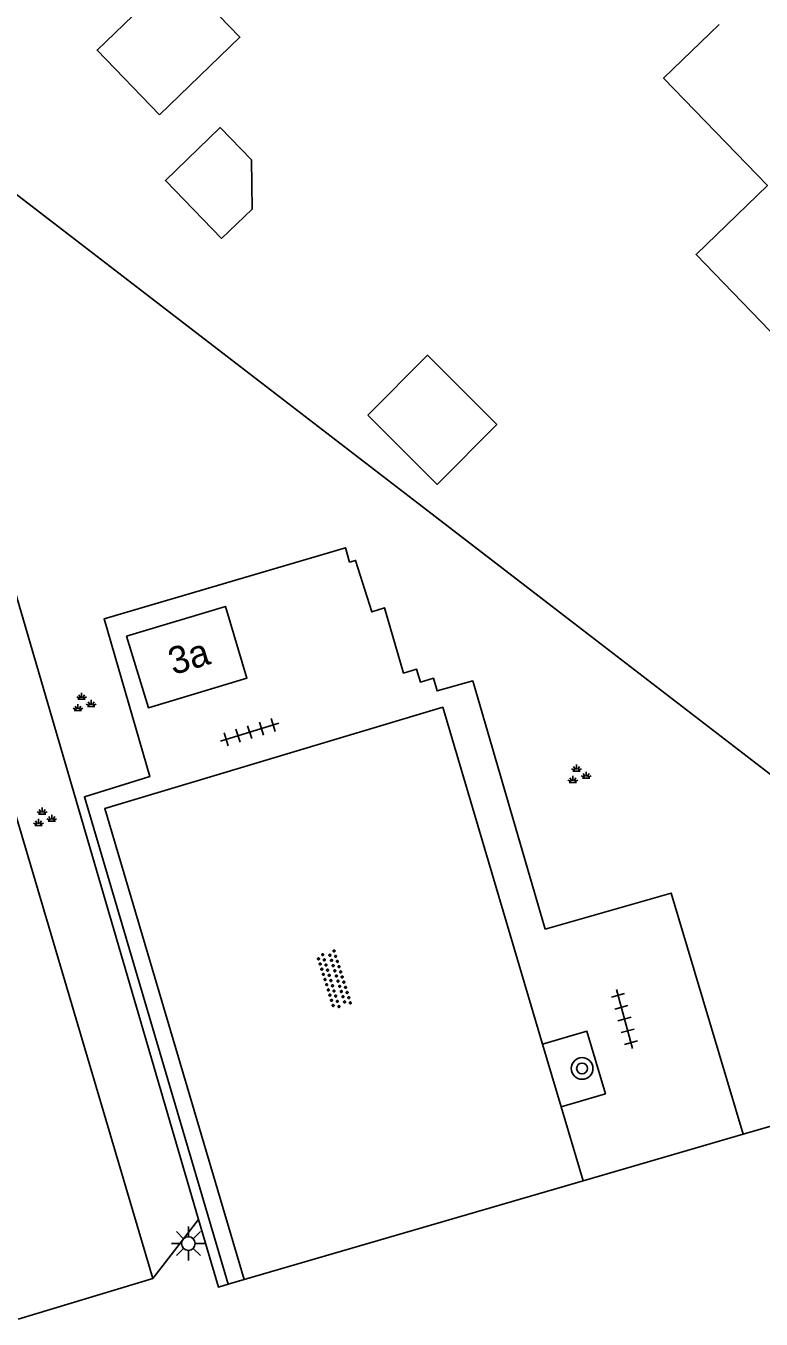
# Model space of a CAD drawing. Extents: x 137999 to 141000, y 397500 to 400501.
# Drawn here: x 138385.02 to 138412.07, y 399270.68 to 399318.29 of the extents above; entities that cross this region are included whole.
import ezdxf

# ---------------------------------------------------------------- set-up
doc = ezdxf.new("R2010")
doc.units = 0
for name, color, linetype in [('gg-afsc-hekwerk', 7, 'Continuous'), ('gg-anno-huisnummerreeks BGT', 7, 'Continuous'), ('gg-bbg-gedigitaliseerde bebouwing', 7, 'Continuous'), ('gg-bbg-gedigitaliseerde bijgebouw', 7, 'Continuous'), ('gg-bbg-hoofdgebouw', 7, 'Continuous'), ('gg-bbg-luifel en loopbrug', 7, 'Continuous'), ('gg-knt-bovenkant onderkant talud', 7, 'Continuous'), ('gg-knt-verharding', 7, 'Continuous'), ('gt-grn-groengrens', 7, 'Continuous'), ('gt-symb-boom', 7, 'Continuous'), ('gt-symb-groenvak', 7, 'Continuous'), ('gt-symb-lichtmast', 7, 'Continuous'), ('gt-symb-overige verharding', 7, 'Continuous'), ('gt-symb-tegel verharding', 7, 'Continuous')]:
    doc.layers.add(name, color=color, linetype=linetype)

# ---------------------------------------------------------------- blocks, each defined once
blk = doc.blocks.new('gt0-GRVAK')
at = {"layer": 'gt-symb-groenvak'}
for p, q in [((-0.11, 0.189), (-0.228, 0.24)), ((-0.182, 0.153), (0.088, 0.153)), ((-0.091, 0.211), (-0.156, 0.322)), ((-0.047, 0.214), (-0.047, 0.393)), ((-0.004, 0.211), (0.061, 0.322)), ((0.015, 0.189), (0.133, 0.24)), ((0.262, -0.052), (0.197, 0.059)), ((0.305, -0.049), (0.305, 0.13)), ((0.349, -0.052), (0.414, 0.059)), ((-0.245, -0.228), (-0.363, -0.177)), ((-0.318, -0.264), (-0.047, -0.264)), ((-0.226, -0.206), (-0.291, -0.095)), ((-0.183, -0.203), (-0.183, -0.024)), ((-0.139, -0.206), (-0.074, -0.095)), ((-0.12, -0.228), (-0.002, -0.177)), ((0.243, -0.074), (0.125, -0.023)), ((0.17, -0.11), (0.441, -0.11)), ((0.368, -0.074), (0.486, -0.023))]:
    blk.add_line(p, q, dxfattribs=at)
blk = doc.blocks.new('gt0-TEG1')
at = {"layer": 'gt-symb-tegel verharding'}
for p, q in [((-1.125, 0), (1.125, 0)), ((-0.9, -0.25), (-0.9, 0.25)), ((-0.45, -0.25), (-0.45, 0.25)), ((0, -0.25), (0, 0.25)), ((0.45, -0.25), (0.45, 0.25)), ((0.9, -0.25), (0.9, 0.25))]:
    blk.add_line(p, q, dxfattribs=at)
blk = doc.blocks.new('gt0-OVH')
at = {"layer": 'gt-symb-overige verharding'}
for points in [[(-0.972, 0.298), (-0.967, 0.308), (-0.965, 0.319), (-0.966, 0.33), (-0.971, 0.34), (-0.978, 0.348), (-0.988, 0.353), (-0.999, 0.355), (-1.01, 0.354), (-1.02, 0.349), (-1.028, 0.342), (-1.033, 0.332), (-1.035, 0.321), (-1.034, 0.31), (-1.029, 0.3), (-1.022, 0.292), (-1.012, 0.287), (-1.001, 0.285), (-0.99, 0.286), (-0.98, 0.291)], [(-0.872, 0.106), (-0.867, 0.116), (-0.865, 0.126), (-0.866, 0.137), (-0.871, 0.147), (-0.878, 0.156), (-0.888, 0.161), (-0.899, 0.163), (-0.91, 0.162), (-0.92, 0.157), (-0.928, 0.15), (-0.933, 0.14), (-0.935, 0.129), (-0.934, 0.118), (-0.929, 0.108), (-0.922, 0.1), (-0.912, 0.095), (-0.901, 0.092), (-0.89, 0.094), (-0.88, 0.098)], [(-0.772, 0.298), (-0.767, 0.308), (-0.765, 0.319), (-0.766, 0.33), (-0.771, 0.34), (-0.778, 0.348), (-0.788, 0.353), (-0.799, 0.355), (-0.81, 0.354), (-0.82, 0.349), (-0.828, 0.342), (-0.833, 0.332), (-0.835, 0.321), (-0.834, 0.31), (-0.829, 0.3), (-0.822, 0.292), (-0.812, 0.287), (-0.801, 0.285), (-0.79, 0.286), (-0.78, 0.291)], [(-0.672, 0.106), (-0.667, 0.116), (-0.665, 0.126), (-0.666, 0.137), (-0.671, 0.147), (-0.678, 0.156), (-0.688, 0.161), (-0.699, 0.163), (-0.71, 0.162), (-0.72, 0.157), (-0.728, 0.15), (-0.733, 0.14), (-0.735, 0.129), (-0.734, 0.118), (-0.729, 0.108), (-0.722, 0.1), (-0.712, 0.095), (-0.701, 0.092), (-0.69, 0.094), (-0.68, 0.098)], [(-0.572, 0.298), (-0.567, 0.308), (-0.565, 0.319), (-0.566, 0.33), (-0.571, 0.34), (-0.578, 0.348), (-0.588, 0.353), (-0.599, 0.355), (-0.61, 0.354), (-0.62, 0.349), (-0.628, 0.342), (-0.633, 0.332), (-0.635, 0.321), (-0.634, 0.31), (-0.629, 0.3), (-0.622, 0.292), (-0.612, 0.287), (-0.601, 0.285), (-0.59, 0.286), (-0.58, 0.291)], [(-0.472, 0.106), (-0.467, 0.116), (-0.465, 0.126), (-0.466, 0.137), (-0.471, 0.147), (-0.478, 0.156), (-0.488, 0.161), (-0.499, 0.163), (-0.51, 0.162), (-0.52, 0.157), (-0.528, 0.15), (-0.533, 0.14), (-0.535, 0.129), (-0.534, 0.118), (-0.529, 0.108), (-0.522, 0.1), (-0.512, 0.095), (-0.501, 0.092), (-0.49, 0.094), (-0.48, 0.098)], [(-0.372, 0.298), (-0.367, 0.308), (-0.365, 0.319), (-0.366, 0.33), (-0.371, 0.34), (-0.378, 0.348), (-0.388, 0.353), (-0.399, 0.355), (-0.41, 0.354), (-0.42, 0.349), (-0.428, 0.342), (-0.433, 0.332), (-0.435, 0.321), (-0.434, 0.31), (-0.429, 0.3), (-0.422, 0.292), (-0.412, 0.287), (-0.401, 0.285), (-0.39, 0.286), (-0.38, 0.291)], [(-0.272, 0.106), (-0.267, 0.116), (-0.265, 0.126), (-0.266, 0.137), (-0.271, 0.147), (-0.278, 0.156), (-0.288, 0.161), (-0.299, 0.163), (-0.31, 0.162), (-0.32, 0.157), (-0.328, 0.15), (-0.333, 0.14), (-0.335, 0.129), (-0.334, 0.118), (-0.329, 0.108), (-0.322, 0.1), (-0.312, 0.095), (-0.301, 0.092), (-0.29, 0.094), (-0.28, 0.098)], [(-0.172, 0.298), (-0.167, 0.308), (-0.165, 0.319), (-0.166, 0.33), (-0.171, 0.34), (-0.178, 0.348), (-0.188, 0.353), (-0.199, 0.355), (-0.21, 0.354), (-0.22, 0.349), (-0.228, 0.342), (-0.233, 0.332), (-0.235, 0.321), (-0.234, 0.31), (-0.229, 0.3), (-0.222, 0.292), (-0.212, 0.287), (-0.201, 0.285), (-0.19, 0.286), (-0.18, 0.291)], [(-0.072, 0.106), (-0.067, 0.116), (-0.065, 0.126), (-0.066, 0.137), (-0.071, 0.147), (-0.078, 0.156), (-0.088, 0.161), (-0.099, 0.163), (-0.11, 0.162), (-0.12, 0.157), (-0.128, 0.15), (-0.133, 0.14), (-0.135, 0.129), (-0.134, 0.118), (-0.129, 0.108), (-0.122, 0.1), (-0.112, 0.095), (-0.101, 0.092), (-0.09, 0.094), (-0.08, 0.098)], [(0.028, 0.298), (0.033, 0.308), (0.035, 0.319), (0.034, 0.33), (0.029, 0.34), (0.022, 0.348), (0.012, 0.353), (0.001, 0.355), (-0.01, 0.354), (-0.02, 0.349), (-0.028, 0.342), (-0.033, 0.332), (-0.035, 0.321), (-0.034, 0.31), (-0.029, 0.3), (-0.022, 0.292), (-0.012, 0.287), (-0.001, 0.285), (0.01, 0.286), (0.02, 0.291)], [(0.128, 0.106), (0.133, 0.116), (0.135, 0.126), (0.134, 0.137), (0.129, 0.147), (0.122, 0.156), (0.112, 0.161), (0.101, 0.163), (0.09, 0.162), (0.08, 0.157), (0.072, 0.15), (0.067, 0.14), (0.065, 0.129), (0.066, 0.118), (0.071, 0.108), (0.078, 0.1), (0.088, 0.095), (0.099, 0.092), (0.11, 0.094), (0.12, 0.098)], [(0.228, 0.298), (0.233, 0.308), (0.235, 0.319), (0.234, 0.33), (0.229, 0.34), (0.222, 0.348), (0.212, 0.353), (0.201, 0.355), (0.19, 0.354), (0.18, 0.349), (0.172, 0.342), (0.167, 0.332), (0.165, 0.321), (0.166, 0.31), (0.171, 0.3), (0.178, 0.292), (0.188, 0.287), (0.199, 0.285), (0.21, 0.286), (0.22, 0.291)], [(0.328, 0.106), (0.333, 0.116), (0.335, 0.126), (0.334, 0.137), (0.329, 0.147), (0.322, 0.156), (0.312, 0.161), (0.301, 0.163), (0.29, 0.162), (0.28, 0.157), (0.272, 0.15), (0.267, 0.14), (0.265, 0.129), (0.266, 0.118), (0.271, 0.108), (0.278, 0.1), (0.288, 0.095), (0.299, 0.092), (0.31, 0.094), (0.32, 0.098)], [(0.428, 0.298), (0.433, 0.308), (0.435, 0.319), (0.434, 0.33), (0.429, 0.34), (0.422, 0.348), (0.412, 0.353), (0.401, 0.355), (0.39, 0.354), (0.38, 0.349), (0.372, 0.342), (0.367, 0.332), (0.365, 0.321), (0.366, 0.31), (0.371, 0.3), (0.378, 0.292), (0.388, 0.287), (0.399, 0.285), (0.41, 0.286), (0.42, 0.291)], [(0.528, 0.106), (0.533, 0.116), (0.535, 0.126), (0.534, 0.137), (0.529, 0.147), (0.522, 0.156), (0.512, 0.161), (0.501, 0.163), (0.49, 0.162), (0.48, 0.157), (0.472, 0.15), (0.467, 0.14), (0.465, 0.129), (0.466, 0.118), (0.471, 0.108), (0.478, 0.1), (0.488, 0.095), (0.499, 0.092), (0.51, 0.094), (0.52, 0.098)], [(0.628, 0.298), (0.633, 0.308), (0.635, 0.319), (0.634, 0.33), (0.629, 0.34), (0.622, 0.348), (0.612, 0.353), (0.601, 0.355), (0.59, 0.354), (0.58, 0.349), (0.572, 0.342), (0.567, 0.332), (0.565, 0.321), (0.566, 0.31), (0.571, 0.3), (0.578, 0.292), (0.588, 0.287), (0.599, 0.285), (0.61, 0.286), (0.62, 0.291)], [(0.728, 0.106), (0.733, 0.116), (0.735, 0.126), (0.734, 0.137), (0.729, 0.147), (0.722, 0.156), (0.712, 0.161), (0.701, 0.163), (0.69, 0.162), (0.68, 0.157), (0.672, 0.15), (0.667, 0.14), (0.665, 0.129), (0.666, 0.118), (0.671, 0.108), (0.678, 0.1), (0.688, 0.095), (0.699, 0.092), (0.71, 0.094), (0.72, 0.098)], [(0.828, 0.298), (0.833, 0.308), (0.835, 0.319), (0.834, 0.33), (0.829, 0.34), (0.822, 0.348), (0.812, 0.353), (0.801, 0.355), (0.79, 0.354), (0.78, 0.349), (0.772, 0.342), (0.767, 0.332), (0.765, 0.321), (0.766, 0.31), (0.771, 0.3), (0.778, 0.292), (0.788, 0.287), (0.799, 0.285), (0.81, 0.286), (0.82, 0.291)], [(0.928, 0.106), (0.933, 0.116), (0.935, 0.126), (0.934, 0.137), (0.929, 0.147), (0.922, 0.156), (0.912, 0.161), (0.901, 0.163), (0.89, 0.162), (0.88, 0.157), (0.872, 0.15), (0.867, 0.14), (0.865, 0.129), (0.866, 0.118), (0.871, 0.108), (0.878, 0.1), (0.888, 0.095), (0.899, 0.092), (0.91, 0.094), (0.92, 0.098)], [(1.028, 0.298), (1.033, 0.308), (1.035, 0.319), (1.034, 0.33), (1.029, 0.34), (1.022, 0.348), (1.012, 0.353), (1.001, 0.355), (0.99, 0.354), (0.98, 0.349), (0.972, 0.342), (0.967, 0.332), (0.965, 0.321), (0.966, 0.31), (0.971, 0.3), (0.978, 0.292), (0.988, 0.287), (0.999, 0.285), (1.01, 0.286), (1.02, 0.291)], [(-0.972, -0.142), (-0.967, -0.132), (-0.965, -0.121), (-0.966, -0.11), (-0.971, -0.1), (-0.978, -0.092), (-0.988, -0.087), (-0.999, -0.085), (-1.01, -0.086), (-1.02, -0.091), (-1.028, -0.098), (-1.033, -0.108), (-1.035, -0.119), (-1.034, -0.13), (-1.029, -0.14), (-1.022, -0.148), (-1.012, -0.153), (-1.001, -0.155), (-0.99, -0.154), (-0.98, -0.149)], [(-0.872, -0.334), (-0.867, -0.324), (-0.865, -0.314), (-0.866, -0.303), (-0.871, -0.293), (-0.878, -0.284), (-0.888, -0.279), (-0.899, -0.277), (-0.91, -0.278), (-0.92, -0.283), (-0.928, -0.29), (-0.933, -0.3), (-0.935, -0.311), (-0.934, -0.322), (-0.929, -0.332), (-0.922, -0.34), (-0.912, -0.345), (-0.901, -0.348), (-0.89, -0.346), (-0.88, -0.342)], [(-0.772, -0.142), (-0.767, -0.132), (-0.765, -0.121), (-0.766, -0.11), (-0.771, -0.1), (-0.778, -0.092), (-0.788, -0.087), (-0.799, -0.085), (-0.81, -0.086), (-0.82, -0.091), (-0.828, -0.098), (-0.833, -0.108), (-0.835, -0.119), (-0.834, -0.13), (-0.829, -0.14), (-0.822, -0.148), (-0.812, -0.153), (-0.801, -0.155), (-0.79, -0.154), (-0.78, -0.149)], [(-0.672, -0.334), (-0.667, -0.324), (-0.665, -0.314), (-0.666, -0.303), (-0.671, -0.293), (-0.678, -0.284), (-0.688, -0.279), (-0.699, -0.277), (-0.71, -0.278), (-0.72, -0.283), (-0.728, -0.29), (-0.733, -0.3), (-0.735, -0.311), (-0.734, -0.322), (-0.729, -0.332), (-0.722, -0.34), (-0.712, -0.345), (-0.701, -0.348), (-0.69, -0.346), (-0.68, -0.342)], [(-0.572, -0.142), (-0.567, -0.132), (-0.565, -0.121), (-0.566, -0.11), (-0.571, -0.1), (-0.578, -0.092), (-0.588, -0.087), (-0.599, -0.085), (-0.61, -0.086), (-0.62, -0.091), (-0.628, -0.098), (-0.633, -0.108), (-0.635, -0.119), (-0.634, -0.13), (-0.629, -0.14), (-0.622, -0.148), (-0.612, -0.153), (-0.601, -0.155), (-0.59, -0.154), (-0.58, -0.149)], [(-0.472, -0.334), (-0.467, -0.324), (-0.465, -0.314), (-0.466, -0.303), (-0.471, -0.293), (-0.478, -0.284), (-0.488, -0.279), (-0.499, -0.277), (-0.51, -0.278), (-0.52, -0.283), (-0.528, -0.29), (-0.533, -0.3), (-0.535, -0.311), (-0.534, -0.322), (-0.529, -0.332), (-0.522, -0.34), (-0.512, -0.345), (-0.501, -0.348), (-0.49, -0.346), (-0.48, -0.342)], [(-0.372, -0.142), (-0.367, -0.132), (-0.365, -0.121), (-0.366, -0.11), (-0.371, -0.1), (-0.378, -0.092), (-0.388, -0.087), (-0.399, -0.085), (-0.41, -0.086), (-0.42, -0.091), (-0.428, -0.098), (-0.433, -0.108), (-0.435, -0.119), (-0.434, -0.13), (-0.429, -0.14), (-0.422, -0.148), (-0.412, -0.153), (-0.401, -0.155), (-0.39, -0.154), (-0.38, -0.149)], [(-0.272, -0.334), (-0.267, -0.324), (-0.265, -0.314), (-0.266, -0.303), (-0.271, -0.293), (-0.278, -0.284), (-0.288, -0.279), (-0.299, -0.277), (-0.31, -0.278), (-0.32, -0.283), (-0.328, -0.29), (-0.333, -0.3), (-0.335, -0.311), (-0.334, -0.322), (-0.329, -0.332), (-0.322, -0.34), (-0.312, -0.345), (-0.301, -0.348), (-0.29, -0.346), (-0.28, -0.342)], [(-0.172, -0.142), (-0.167, -0.132), (-0.165, -0.121), (-0.166, -0.11), (-0.171, -0.1), (-0.178, -0.092), (-0.188, -0.087), (-0.199, -0.085), (-0.21, -0.086), (-0.22, -0.091), (-0.228, -0.098), (-0.233, -0.108), (-0.235, -0.119), (-0.234, -0.13), (-0.229, -0.14), (-0.222, -0.148), (-0.212, -0.153), (-0.201, -0.155), (-0.19, -0.154), (-0.18, -0.149)], [(-0.072, -0.334), (-0.067, -0.324), (-0.065, -0.314), (-0.066, -0.303), (-0.071, -0.293), (-0.078, -0.284), (-0.088, -0.279), (-0.099, -0.277), (-0.11, -0.278), (-0.12, -0.283), (-0.128, -0.29), (-0.133, -0.3), (-0.135, -0.311), (-0.134, -0.322), (-0.129, -0.332), (-0.122, -0.34), (-0.112, -0.345), (-0.101, -0.348), (-0.09, -0.346), (-0.08, -0.342)], [(0.028, -0.142), (0.033, -0.132), (0.035, -0.121), (0.034, -0.11), (0.029, -0.1), (0.022, -0.092), (0.012, -0.087), (0.001, -0.085), (-0.01, -0.086), (-0.02, -0.091), (-0.028, -0.098), (-0.033, -0.108), (-0.035, -0.119), (-0.034, -0.13), (-0.029, -0.14), (-0.022, -0.148), (-0.012, -0.153), (-0.001, -0.155), (0.01, -0.154), (0.02, -0.149)], [(0.128, -0.334), (0.133, -0.324), (0.135, -0.314), (0.134, -0.303), (0.129, -0.293), (0.122, -0.284), (0.112, -0.279), (0.101, -0.277), (0.09, -0.278), (0.08, -0.283), (0.072, -0.29), (0.067, -0.3), (0.065, -0.311), (0.066, -0.322), (0.071, -0.332), (0.078, -0.34), (0.088, -0.345), (0.099, -0.348), (0.11, -0.346), (0.12, -0.342)], [(0.228, -0.142), (0.233, -0.132), (0.235, -0.121), (0.234, -0.11), (0.229, -0.1), (0.222, -0.092), (0.212, -0.087), (0.201, -0.085), (0.19, -0.086), (0.18, -0.091), (0.172, -0.098), (0.167, -0.108), (0.165, -0.119), (0.166, -0.13), (0.171, -0.14), (0.178, -0.148), (0.188, -0.153), (0.199, -0.155), (0.21, -0.154), (0.22, -0.149)], [(0.328, -0.334), (0.333, -0.324), (0.335, -0.314), (0.334, -0.303), (0.329, -0.293), (0.322, -0.284), (0.312, -0.279), (0.301, -0.277), (0.29, -0.278), (0.28, -0.283), (0.272, -0.29), (0.267, -0.3), (0.265, -0.311), (0.266, -0.322), (0.271, -0.332), (0.278, -0.34), (0.288, -0.345), (0.299, -0.348), (0.31, -0.346), (0.32, -0.342)], [(0.428, -0.142), (0.433, -0.132), (0.435, -0.121), (0.434, -0.11), (0.429, -0.1), (0.422, -0.092), (0.412, -0.087), (0.401, -0.085), (0.39, -0.086), (0.38, -0.091), (0.372, -0.098), (0.367, -0.108), (0.365, -0.119), (0.366, -0.13), (0.371, -0.14), (0.378, -0.148), (0.388, -0.153), (0.399, -0.155), (0.41, -0.154), (0.42, -0.149)], [(0.528, -0.334), (0.533, -0.324), (0.535, -0.314), (0.534, -0.303), (0.529, -0.293), (0.522, -0.284), (0.512, -0.279), (0.501, -0.277), (0.49, -0.278), (0.48, -0.283), (0.472, -0.29), (0.467, -0.3), (0.465, -0.311), (0.466, -0.322), (0.471, -0.332), (0.478, -0.34), (0.488, -0.345), (0.499, -0.348), (0.51, -0.346), (0.52, -0.342)], [(0.628, -0.142), (0.633, -0.132), (0.635, -0.121), (0.634, -0.11), (0.629, -0.1), (0.622, -0.092), (0.612, -0.087), (0.601, -0.085), (0.59, -0.086), (0.58, -0.091), (0.572, -0.098), (0.567, -0.108), (0.565, -0.119), (0.566, -0.13), (0.571, -0.14), (0.578, -0.148), (0.588, -0.153), (0.599, -0.155), (0.61, -0.154), (0.62, -0.149)], [(0.728, -0.334), (0.733, -0.324), (0.735, -0.314), (0.734, -0.303), (0.729, -0.293), (0.722, -0.284), (0.712, -0.279), (0.701, -0.277), (0.69, -0.278), (0.68, -0.283), (0.672, -0.29), (0.667, -0.3), (0.665, -0.311), (0.666, -0.322), (0.671, -0.332), (0.678, -0.34), (0.688, -0.345), (0.699, -0.348), (0.71, -0.346), (0.72, -0.342)], [(0.828, -0.142), (0.833, -0.132), (0.835, -0.121), (0.834, -0.11), (0.829, -0.1), (0.822, -0.092), (0.812, -0.087), (0.801, -0.085), (0.79, -0.086), (0.78, -0.091), (0.772, -0.098), (0.767, -0.108), (0.765, -0.119), (0.766, -0.13), (0.771, -0.14), (0.778, -0.148), (0.788, -0.153), (0.799, -0.155), (0.81, -0.154), (0.82, -0.149)], [(0.928, -0.334), (0.933, -0.324), (0.935, -0.314), (0.934, -0.303), (0.929, -0.293), (0.922, -0.284), (0.912, -0.279), (0.901, -0.277), (0.89, -0.278), (0.88, -0.283), (0.872, -0.29), (0.867, -0.3), (0.865, -0.311), (0.866, -0.322), (0.871, -0.332), (0.878, -0.34), (0.888, -0.345), (0.899, -0.348), (0.91, -0.346), (0.92, -0.342)], [(1.028, -0.142), (1.033, -0.132), (1.035, -0.121), (1.034, -0.11), (1.029, -0.1), (1.022, -0.092), (1.012, -0.087), (1.001, -0.085), (0.99, -0.086), (0.98, -0.091), (0.972, -0.098), (0.967, -0.108), (0.965, -0.119), (0.966, -0.13), (0.971, -0.14), (0.978, -0.148), (0.988, -0.153), (0.999, -0.155), (1.01, -0.154), (1.02, -0.149)]]:
    blk.add_lwpolyline(points, close=True, dxfattribs=at)
blk = doc.blocks.new('gt0-LMAST')
at = {"layer": 'gt-symb-lichtmast'}
for p, q in [((-0.005, 0.246), (-0.005, 0.621)), ((-0.182, 0.173), (-0.447, 0.438)), ((0.172, 0.173), (0.437, 0.438)), ((-0.255, -0.004), (-0.63, -0.004)), ((-0.182, -0.181), (-0.447, -0.446)), ((-0.005, -0.254), (-0.005, -0.629)), ((0.437, -0.446), (0.172, -0.181)), ((0.245, -0.004), (0.62, -0.004))]:
    blk.add_line(p, q, dxfattribs=at)
blk.add_circle((-0.005, -0.004), 0.25, dxfattribs=at)
blk = doc.blocks.new('gt0-BOOM')
at = {"layer": 'gt-symb-boom'}
for radius in [0.4, 0.2]:
    blk.add_circle((0, 0), radius, dxfattribs=at)

msp = doc.modelspace()

# ---------------------------------------------------------------- linework, layer by layer
at = {"layer": 'gg-afsc-hekwerk'}
for p, q in [((138391.371, 399274.355), (138382.321, 399305.317)), ((138411.417, 399277.486), (138414.756, 399278.458)), ((138405.521, 399275.77), (138411.417, 399277.486)), ((138393.049, 399272.139), (138405.521, 399275.77)), ((138389.691, 399272.175), (138391.371, 399274.355)), ((138389.691, 399272.175), (138384.731, 399270.682)), ((138392.46, 399271.968), (138393.049, 399272.139))]:
    msp.add_line(p, q, dxfattribs=at)
msp.add_lwpolyline([(138391.371, 399274.355), (138392.099, 399271.863), (138392.46, 399271.968)], dxfattribs=at)
at = {"layer": 'gg-bbg-gedigitaliseerde bebouwing'}
msp.add_lwpolyline([(138412.728, 399306.719), (138409.68, 399309.866), (138412.306, 399312.411), (138408.485, 399316.356), (138410.524, 399318.332)], dxfattribs=at)
at = {"layer": 'gg-bbg-gedigitaliseerde bijgebouw'}
for points in [[(138389.929, 399315.013), (138387.634, 399317.392), (138390.593, 399320.247), (138392.889, 399317.868), (138389.929, 399315.013)], [(138392.216, 399310.458), (138393.34, 399311.543), (138393.314, 399313.356), (138392.168, 399314.543), (138390.152, 399312.597), (138392.216, 399310.458)]]:
    msp.add_lwpolyline(points, dxfattribs=at)
at = {"layer": 'gg-bbg-hoofdgebouw'}
msp.add_lwpolyline([(138388.724, 399295.823), (138389.525, 399293.186), (138393.15, 399294.272), (138392.358, 399296.916), (138388.724, 399295.823)], dxfattribs=at)
at = {"layer": 'gg-bbg-luifel en loopbrug'}
msp.add_lwpolyline([(138397.596, 399303.957), (138399.797, 399306.158), (138402.346, 399303.611), (138400.145, 399301.409), (138397.596, 399303.957)], dxfattribs=at)
at = {"layer": 'gg-knt-bovenkant onderkant talud'}
msp.add_line((138389.691, 399272.175), (138380.077, 399304.657), dxfattribs=at)
at = {"layer": 'gg-knt-verharding'}
for p, q in [((138404.03, 399280.804), (138404.712, 399278.502)), ((138404.712, 399278.502), (138405.521, 399275.77))]:
    msp.add_line(p, q, dxfattribs=at)
for points in [[(138411.417, 399277.486), (138408.763, 399286.366), (138404.126, 399285.042), (138401.463, 399294.173), (138400.149, 399293.807), (138400.012, 399294.273), (138399.533, 399294.132), (138399.394, 399294.602), (138398.913, 399294.463), (138398.218, 399296.865), (138397.741, 399296.715), (138397.148, 399298.612), (138396.927, 399298.547), (138396.772, 399299.075), (138387.894, 399296.459), (138389.576, 399290.654), (138387.172, 399289.908), (138392.46, 399271.968)], [(138393.049, 399272.139), (138387.92, 399289.482), (138400.357, 399293.202), (138404.03, 399280.804)], [(138404.712, 399278.502), (138406.344, 399278.977), (138405.662, 399281.279), (138404.03, 399280.804)]]:
    msp.add_lwpolyline(points, dxfattribs=at)
at = {"layer": 'gt-grn-groengrens'}
msp.add_lwpolyline([(138366.985, 399331.751), (138379.658, 399315.927), (138424.631, 399281.333)], dxfattribs=at)

# ---------------------------------------------------------------- block references
at = {"layer": 'gt-symb-boom'}
msp.add_blockref('gt0-BOOM', (138405.484, 399279.909), dxfattribs=at)
at = {"layer": 'gt-symb-groenvak'}
for p in [(138387.114, 399293.343), (138405.327, 399290.703), (138385.662, 399289.118)]:
    msp.add_blockref('gt0-GRVAK', p, dxfattribs=at)
at = {"layer": 'gt-symb-lichtmast'}
msp.add_blockref('gt0-LMAST', (138391.001, 399273.467), dxfattribs=at)
at = {"layer": 'gt-symb-overige verharding', "rotation": -72.54344186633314}
msp.add_blockref('gt0-OVH', (138396.352, 399283.18), dxfattribs=at)
at = {"layer": 'gt-symb-tegel verharding'}
for p, rotation in [((138393.251, 399292.287), 17.220699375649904), ((138407.043, 399281.728), -74.7549296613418)]:
    msp.add_blockref('gt0-TEG1', p, dxfattribs=dict(at, rotation=rotation))

# ---------------------------------------------------------------- texts
at = {"layer": 'gg-anno-huisnummerreeks BGT'}
msp.add_text('3a', height=1, rotation=16.9, dxfattribs=at).set_placement((138390.44, 399294.382))

doc.saveas('drawing.dxf')
